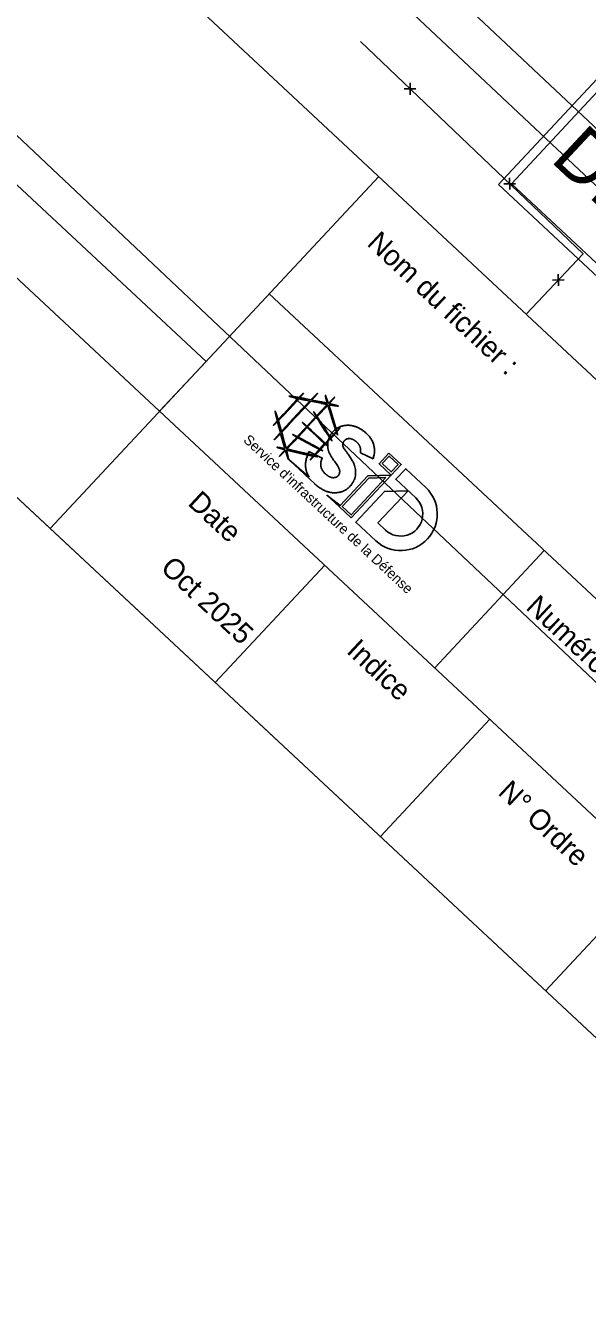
# Model space of a CAD drawing. Extents: x 343997 to 344255, y 298512 to 298767.
# Drawn here: x 344119.17 to 344139.61, y 298518.23 to 298564.4 of the extents above; entities that cross this region are included whole.
import ezdxf

# ---------------------------------------------------------------- set-up
doc = ezdxf.new("R2010")
doc.units = 0
for name, color, linetype in [('DH_CADRE -CARTOUCHE', 7, 'Continuous'), ('GO_DALLE', 7, 'Continuous'), ('PS_PLATE', 7, 'Continuous'), ('PS_WELD', 7, 'Continuous'), ('RES_TELEPHONE SOUTERRAIN', 7, 'Continuous')]:
    doc.layers.add(name, color=color, linetype=linetype)

msp = doc.modelspace()

# ---------------------------------------------------------------- linework, layer by layer
at = {"layer": 'DH_CADRE -CARTOUCHE'}
for p, q in [((344132.013, 298558.901), (344120.073, 298546.107)), ((344128.033, 298554.636), (344146.034, 298537.838)), ((344129.379, 298550.821), (344129.554, 298550.786)), ((344124.053, 298550.372), (344151.163, 298525.072)), ((344128.551, 298550.27), (344128.887, 298550.63)), ((344128.912, 298550.606), (344128.576, 298550.246)), ((344128.751, 298549.932), (344129.237, 298550.453)), ((344129.263, 298550.429), (344128.777, 298549.909)), ((344129.512, 298550.742), (344129.369, 298550.771)), ((344129.925, 298550.659), (344129.544, 298550.736)), ((344129.583, 298550.78), (344129.935, 298550.709)), ((344130.345, 298549.999), (344130.208, 298550.446)), ((344130.248, 298550.458), (344130.385, 298550.012)), ((344129.406, 298549.827), (344129.74, 298550.185)), ((344129.758, 298550.154), (344129.432, 298549.804)), ((344129.758, 298550.204), (344129.857, 298550.311)), ((344129.883, 298550.287), (344129.778, 298550.175)), ((344130.074, 298549.648), (344129.867, 298549.974)), ((344129.897, 298549.993), (344130.103, 298549.667)), ((344128.441, 298549.593), (344128.394, 298549.765)), ((344128.443, 298549.779), (344128.482, 298549.638)), ((344128.544, 298549.218), (344128.449, 298549.564)), ((344128.49, 298549.607), (344128.593, 298549.232)), ((344128.936, 298549.323), (344129.035, 298549.43)), ((344129.066, 298549.412), (344128.961, 298549.3)), ((344129.053, 298549.449), (344129.387, 298549.807)), ((344129.412, 298549.783), (344129.086, 298549.433)), ((344129.824, 298549.395), (344129.542, 298549.658)), ((344129.565, 298549.683), (344129.848, 298549.42)), ((344128.826, 298548.964), (344129.28, 298548.858)), ((344129.596, 298549.123), (344129.256, 298549.306)), ((344129.272, 298549.337), (344129.612, 298549.153)), ((344129.889, 298549.021), (344130.05, 298549.193)), ((344130.077, 298549.171), (344129.914, 298548.997)), ((344130.064, 298549.209), (344130.225, 298549.381)), ((344130.251, 298549.357), (344130.088, 298549.183)), ((344128.759, 298548.601), (344129.692, 298547.73)), ((344129.486, 298547.971), (344128.759, 298548.601)), ((344129.271, 298548.817), (344128.816, 298548.923)), ((344131.352, 298548.862), (344131.81, 298548.639)), ((344138.032, 298545.305), (344134.052, 298541.041)), ((344130.054, 298544.772), (344126.074, 298540.507)), ((344150.014, 298542.103), (344138.074, 298529.308)), ((344136.054, 298539.173), (344132.074, 298534.908))]:
    msp.add_line(p, q, dxfattribs=at)
for points in [[(343997.309, 298660.673), (344147.183, 298520.807), (344245.09, 298625.72), (344095.215, 298765.586)], [(344086.014, 298601.829), (344159.123, 298533.601), (344147.183, 298520.807), (344074.074, 298589.035)], [(344098.957, 298577.174), (344125.741, 298552.18), (344124.053, 298550.372), (344097.27, 298575.367)], [(344136.369, 298558.619), (344159.002, 298537.497), (344162.924, 298541.7), (344140.291, 298562.822)], [(344140.308, 298562.353), (344162.455, 298541.684), (344158.986, 298537.967), (344136.838, 298558.635)], [(344132.388, 298548.849), (344132.833, 298548.434), (344132.473, 298548.049), (344132.029, 298548.464)], [(344132.144, 298548.468), (344132.469, 298548.164), (344132.717, 298548.43), (344132.392, 298548.734)], [(344131.019, 298546.491), (344130.575, 298546.906), (344130.133, 298547.318), (344130.609, 298546.943), (344131.614, 298548.019), (344132.473, 298548.049)], [(344132.279, 298547.961), (344131.65, 298547.939), (344130.69, 298546.91), (344131.015, 298546.606)]]:
    msp.add_lwpolyline(points, close=True, dxfattribs=at)
for points in [[(344129.943, 298548.63), (344129.962, 298548.67), (344129.48, 298548.905)], [(344133.36, 298547.221), (344132.636, 298547.897), (344132.995, 298548.283), (344133.727, 298547.6)], [(344131.913, 298545.657), (344131.182, 298546.339), (344132.221, 298547.453), (344133.08, 298547.483), (344131.986, 298546.31), (344132.266, 298546.049)]]:
    msp.add_lwpolyline(points, dxfattribs=at)
for radius, start, end in [(1.329, 227.4033, 46.5536), (0.802, 226.9784, 46.9784)]:
    msp.add_arc((344132.813, 298546.635), radius, start, end, dxfattribs=at)
for points, degree in [([(344129.082, 298550.834), (344128.942, 298550.866), (344128.815, 298550.898), (344128.75, 298550.922)], 2), ([(344128.75, 298550.922), (344128.823, 298550.919), (344128.966, 298550.897), (344129.118, 298550.87)], 2), ([(344128.911, 298550.655), (344128.965, 298550.713), (344129.025, 298550.776), (344129.082, 298550.834)], 2), ([(344129.112, 298550.827), (344129.056, 298550.763), (344128.993, 298550.694), (344128.936, 298550.632)], 2), ([(344129.33, 298550.779), (344129.26, 298550.794), (344129.185, 298550.81), (344129.112, 298550.827)], 2), ([(344129.118, 298550.87), (344129.183, 298550.936), (344129.241, 298550.993), (344129.277, 298551.023)], 2), ([(344129.277, 298551.023), (344129.251, 298550.987), (344129.203, 298550.93), (344129.146, 298550.865)], 2), ([(344129.146, 298550.865), (344129.211, 298550.853), (344129.278, 298550.841), (344129.34, 298550.829)], 2), ([(344129.34, 298550.829), (344129.353, 298550.826), (344129.366, 298550.824), (344129.379, 298550.821)], 2), ([(344129.554, 298550.786), (344129.654, 298550.889), (344129.743, 298550.978), (344129.795, 298551.026)], 2), ([(344129.795, 298551.026), (344129.753, 298550.972), (344129.675, 298550.882), (344129.583, 298550.78)], 2), ([(344130.144, 298550.664), (344130.111, 298550.783), (344130.083, 298550.895), (344130.074, 298550.953)], 2), ([(344130.074, 298550.953), (344130.101, 298550.897), (344130.143, 298550.779), (344130.185, 298550.655)], 2), ([(344130.185, 298550.655), (344130.281, 298550.753), (344130.365, 298550.838), (344130.416, 298550.884)], 2), ([(344130.416, 298550.884), (344130.375, 298550.832), (344130.3, 298550.746), (344130.213, 298550.649)], 2), ([(344128.327, 298550.023), (344128.29, 298550.172), (344128.258, 298550.313), (344128.25, 298550.386)], 2), ([(344128.25, 298550.386), (344128.278, 298550.323), (344128.319, 298550.198), (344128.361, 298550.061)], 2), ([(344128.887, 298550.63), (344128.895, 298550.638), (344128.903, 298550.647), (344128.911, 298550.655)], 2), ([(344128.936, 298550.632), (344128.928, 298550.623), (344128.92, 298550.615), (344128.912, 298550.606)], 2), ([(344129.237, 298550.453), (344129.249, 298550.465), (344129.26, 298550.477), (344129.272, 298550.49)], 2), ([(344129.297, 298550.466), (344129.285, 298550.454), (344129.274, 298550.441), (344129.263, 298550.429)], 2), ([(344129.272, 298550.49), (344129.349, 298550.571), (344129.433, 298550.66), (344129.512, 298550.742)], 2), ([(344129.544, 298550.736), (344129.464, 298550.647), (344129.377, 298550.553), (344129.297, 298550.466)], 2), ([(344129.369, 298550.771), (344129.356, 298550.774), (344129.343, 298550.777), (344129.33, 298550.779)], 2), ([(344129.74, 298550.185), (344129.7, 298550.253), (344129.666, 298550.314), (344129.65, 298550.35)], 2), ([(344129.65, 298550.35), (344129.676, 298550.321), (344129.715, 298550.267), (344129.758, 298550.204)], 2), ([(344129.857, 298550.311), (344129.869, 298550.323), (344129.88, 298550.335), (344129.892, 298550.348)], 2), ([(344129.892, 298550.348), (344129.974, 298550.435), (344130.064, 298550.53), (344130.149, 298550.617)], 2), ([(344130.164, 298550.594), (344130.084, 298550.506), (344129.997, 298550.411), (344129.917, 298550.324)], 2), ([(344129.965, 298550.651), (344129.951, 298550.654), (344129.938, 298550.657), (344129.925, 298550.659)], 2), ([(344129.935, 298550.709), (344129.948, 298550.706), (344129.961, 298550.704), (344129.975, 298550.701)], 2), ([(344130.149, 298550.617), (344130.086, 298550.628), (344130.024, 298550.64), (344129.965, 298550.651)], 2), ([(344129.975, 298550.701), (344130.029, 298550.689), (344130.087, 298550.677), (344130.144, 298550.664)], 2), ([(344130.199, 298550.477), (344130.187, 298550.515), (344130.176, 298550.555), (344130.164, 298550.594)], 2), ([(344130.185, 298550.655), (344130.185, 298550.655), (344130.185, 298550.655), (344130.185, 298550.655)], 2), ([(344130.208, 298550.446), (344130.205, 298550.456), (344130.202, 298550.467), (344130.199, 298550.477)], 2), ([(344130.555, 298550.558), (344130.484, 298550.561), (344130.347, 298550.582), (344130.2, 298550.608)], 2), ([(344130.2, 298550.608), (344130.213, 298550.568), (344130.226, 298550.528), (344130.238, 298550.49)], 2), ([(344130.213, 298550.649), (344130.356, 298550.616), (344130.489, 298550.583), (344130.555, 298550.558)], 2), ([(344130.238, 298550.49), (344130.242, 298550.479), (344130.245, 298550.468), (344130.248, 298550.458)], 2), ([(344128.186, 298549.853), (344128.213, 298549.891), (344128.266, 298549.953), (344128.327, 298550.023)], 2), ([(344128.334, 298549.995), (344128.273, 298549.934), (344128.22, 298549.882), (344128.186, 298549.853)], 2), ([(344128.383, 298549.804), (344128.367, 298549.865), (344128.35, 298549.93), (344128.334, 298549.995)], 2), ([(344128.361, 298550.061), (344128.415, 298550.121), (344128.473, 298550.186), (344128.527, 298550.244)], 2), ([(344128.552, 298550.221), (344128.494, 298550.159), (344128.43, 298550.092), (344128.37, 298550.031)], 2), ([(344128.37, 298550.031), (344128.391, 298549.96), (344128.413, 298549.886), (344128.432, 298549.817)], 2), ([(344128.482, 298549.638), (344128.558, 298549.723), (344128.641, 298549.813), (344128.717, 298549.895)], 2), ([(344128.742, 298549.872), (344128.662, 298549.786), (344128.573, 298549.693), (344128.49, 298549.607)], 2), ([(344128.527, 298550.244), (344128.535, 298550.253), (344128.543, 298550.261), (344128.551, 298550.27)], 2), ([(344128.576, 298550.246), (344128.568, 298550.238), (344128.56, 298550.229), (344128.552, 298550.221)], 2), ([(344128.717, 298549.895), (344128.729, 298549.908), (344128.74, 298549.92), (344128.751, 298549.932)], 2), ([(344128.777, 298549.909), (344128.765, 298549.897), (344128.754, 298549.884), (344128.742, 298549.872)], 2), ([(344129.387, 298549.807), (344129.322, 298549.872), (344129.264, 298549.932), (344129.236, 298549.967)], 2), ([(344129.236, 298549.967), (344129.273, 298549.942), (344129.337, 298549.888), (344129.406, 298549.827)], 2), ([(344129.853, 298549.998), (344129.822, 298550.047), (344129.789, 298550.102), (344129.758, 298550.154)], 2), ([(344129.778, 298550.175), (344129.813, 298550.123), (344129.849, 298550.067), (344129.882, 298550.016)], 2), ([(344129.867, 298549.974), (344129.863, 298549.982), (344129.858, 298549.99), (344129.853, 298549.998)], 2), ([(344129.882, 298550.016), (344129.887, 298550.008), (344129.892, 298550), (344129.897, 298549.993)], 2), ([(344129.917, 298550.324), (344129.906, 298550.312), (344129.894, 298550.299), (344129.883, 298550.287)], 2), ([(344130.355, 298549.968), (344130.352, 298549.978), (344130.349, 298549.989), (344130.345, 298549.999)], 2), ([(344130.468, 298549.633), (344130.432, 298549.73), (344130.39, 298549.857), (344130.355, 298549.968)], 2), ([(344130.385, 298550.012), (344130.389, 298550.001), (344130.392, 298549.991), (344130.395, 298549.98)], 2), ([(344130.395, 298549.98), (344130.427, 298549.873), (344130.462, 298549.751), (344130.487, 298549.652)], 2), ([(344128.218, 298549.336), (344128.262, 298549.392), (344128.345, 298549.486), (344128.441, 298549.593)], 2), ([(344128.449, 298549.564), (344128.354, 298549.466), (344128.269, 298549.382), (344128.218, 298549.336)], 2), ([(344128.394, 298549.765), (344128.39, 298549.778), (344128.387, 298549.791), (344128.383, 298549.804)], 2), ([(344128.432, 298549.817), (344128.436, 298549.804), (344128.439, 298549.791), (344128.443, 298549.779)], 2), ([(344129.035, 298549.43), (344128.97, 298549.469), (344128.913, 298549.504), (344128.882, 298549.527)], 2), ([(344128.882, 298549.527), (344128.919, 298549.514), (344128.983, 298549.485), (344129.053, 298549.449)], 2), ([(344129.232, 298549.319), (344129.178, 298549.349), (344129.12, 298549.381), (344129.066, 298549.412)], 2), ([(344129.086, 298549.433), (344129.14, 298549.406), (344129.196, 298549.377), (344129.248, 298549.349)], 2), ([(344129.522, 298549.677), (344129.486, 298549.711), (344129.448, 298549.747), (344129.412, 298549.783)], 2), ([(344129.432, 298549.804), (344129.47, 298549.77), (344129.509, 298549.735), (344129.545, 298549.702)], 2), ([(344129.542, 298549.658), (344129.535, 298549.664), (344129.528, 298549.671), (344129.522, 298549.677)], 2), ([(344129.545, 298549.702), (344129.552, 298549.696), (344129.559, 298549.69), (344129.565, 298549.683)], 2), ([(344129.848, 298549.42), (344129.854, 298549.414), (344129.861, 298549.408), (344129.868, 298549.401)], 2), ([(344130.088, 298549.625), (344130.083, 298549.633), (344130.079, 298549.64), (344130.074, 298549.648)], 2), ([(344130.24, 298549.397), (344130.193, 298549.465), (344130.137, 298549.55), (344130.088, 298549.625)], 2), ([(344130.103, 298549.667), (344130.108, 298549.659), (344130.113, 298549.651), (344130.118, 298549.643)], 2), ([(344130.118, 298549.643), (344130.164, 298549.569), (344130.215, 298549.484), (344130.256, 298549.413)], 2), ([(344130.307, 298549.577), (344130.178, 298549.408), (344130.163, 298549.211)], 2), ([(344130.256, 298549.413), (344130.324, 298549.485), (344130.4, 298549.565), (344130.468, 298549.633)], 2), ([(344130.477, 298549.607), (344130.414, 298549.535), (344130.341, 298549.455), (344130.274, 298549.383)], 2), ([(344130.83, 298549.858), (344130.503, 298549.831), (344130.307, 298549.577)], 2), ([(344130.519, 298549.504), (344130.508, 298549.529), (344130.493, 298549.564), (344130.477, 298549.607)], 2), ([(344130.487, 298549.652), (344130.54, 298549.705), (344130.585, 298549.748), (344130.615, 298549.774)], 2), ([(344130.615, 298549.774), (344130.591, 298549.74), (344130.546, 298549.687), (344130.493, 298549.626)], 2), ([(344130.493, 298549.626), (344130.506, 298549.576), (344130.515, 298549.533), (344130.519, 298549.504)], 2), ([(344131.474, 298549.644), (344131.157, 298549.885), (344130.83, 298549.858)], 2), ([(344131.81, 298548.639), (344132.002, 298549.242), (344131.474, 298549.644)], 2), ([(344128.615, 298548.973), (344128.488, 298549.006), (344128.368, 298549.04), (344128.31, 298549.063)], 2), ([(344128.31, 298549.063), (344128.369, 298549.058), (344128.482, 298549.038), (344128.603, 298549.013)], 2), ([(344128.403, 298548.727), (344128.445, 298548.781), (344128.524, 298548.871), (344128.615, 298548.973)], 2), ([(344128.623, 298548.945), (344128.532, 298548.851), (344128.452, 298548.771), (344128.403, 298548.727)], 2), ([(344128.555, 298549.179), (344128.551, 298549.193), (344128.548, 298549.205), (344128.544, 298549.218)], 2), ([(344128.603, 298549.013), (344128.586, 298549.069), (344128.57, 298549.126), (344128.555, 298549.179)], 2), ([(344128.593, 298549.232), (344128.597, 298549.219), (344128.6, 298549.206), (344128.604, 298549.193)], 2), ([(344128.604, 298549.193), (344128.619, 298549.135), (344128.635, 298549.073), (344128.65, 298549.012)], 2), ([(344128.615, 298548.973), (344128.615, 298548.973), (344128.615, 298548.973), (344128.615, 298548.973)], 2), ([(344128.737, 298548.611), (344128.708, 298548.675), (344128.666, 298548.805), (344128.623, 298548.945)], 2), ([(344128.65, 298549.012), (344128.732, 298549.102), (344128.82, 298549.198), (344128.901, 298549.286)], 2), ([(344128.784, 298548.931), (344128.745, 298548.941), (344128.704, 298548.951), (344128.663, 298548.961)], 2), ([(344128.663, 298548.961), (344128.699, 298548.817), (344128.729, 298548.681), (344128.737, 298548.611)], 2), ([(344128.926, 298549.263), (344128.846, 298549.177), (344128.757, 298549.084), (344128.674, 298548.998)], 2), ([(344128.674, 298548.998), (344128.715, 298548.989), (344128.755, 298548.98), (344128.793, 298548.972)], 2), ([(344128.793, 298548.972), (344128.804, 298548.969), (344128.815, 298548.967), (344128.826, 298548.964)], 2), ([(344128.901, 298549.286), (344128.913, 298549.299), (344128.924, 298549.311), (344128.936, 298549.323)], 2), ([(344128.961, 298549.3), (344128.95, 298549.287), (344128.938, 298549.275), (344128.926, 298549.263)], 2), ([(344129.256, 298549.306), (344129.248, 298549.31), (344129.24, 298549.315), (344129.232, 298549.319)], 2), ([(344129.248, 298549.349), (344129.256, 298549.345), (344129.264, 298549.341), (344129.272, 298549.337)], 2), ([(344129.62, 298549.11), (344129.612, 298549.114), (344129.604, 298549.119), (344129.596, 298549.123)], 2), ([(344129.612, 298549.153), (344129.62, 298549.149), (344129.628, 298549.145), (344129.636, 298549.14)], 2), ([(344129.859, 298548.988), (344129.785, 298549.024), (344129.697, 298549.069), (344129.62, 298549.11)], 2), ([(344129.636, 298549.14), (344129.715, 298549.097), (344129.803, 298549.047), (344129.874, 298549.005)], 2), ([(344129.655, 298548.761), (344129.718, 298548.833), (344129.792, 298548.915), (344129.859, 298548.988)], 2), ([(344129.89, 298548.971), (344129.823, 298548.9), (344129.748, 298548.822), (344129.681, 298548.754)], 2), ([(344129.844, 298549.376), (344129.837, 298549.382), (344129.831, 298549.389), (344129.824, 298549.395)], 2), ([(344130.05, 298549.193), (344129.986, 298549.247), (344129.91, 298549.315), (344129.844, 298549.376)], 2), ([(344129.868, 298549.401), (344129.933, 298549.339), (344130.006, 298549.268), (344130.064, 298549.209)], 2), ([(344129.874, 298549.005), (344129.879, 298549.01), (344129.884, 298549.015), (344129.889, 298549.021)], 2), ([(344129.892, 298548.973), (344129.891, 298548.972), (344129.891, 298548.972), (344129.89, 298548.971)], 2), ([(344129.986, 298548.932), (344129.963, 298548.94), (344129.93, 298548.955), (344129.892, 298548.973)], 2), ([(344129.914, 298548.997), (344129.911, 298548.993), (344129.908, 298548.99), (344129.904, 298548.986)], 2), ([(344129.904, 298548.986), (344129.939, 298548.965), (344129.967, 298548.946), (344129.986, 298548.932)], 2), ([(344130.153, 298549.111), (344130.134, 298549.124), (344130.107, 298549.145), (344130.077, 298549.171)], 2), ([(344130.088, 298549.183), (344130.116, 298549.155), (344130.139, 298549.13), (344130.153, 298549.111)], 2), ([(344130.163, 298549.211), (344130.149, 298549.013), (344130.219, 298548.855)], 2), ([(344130.225, 298549.381), (344130.23, 298549.386), (344130.235, 298549.391), (344130.24, 298549.397)], 2), ([(344130.261, 298549.368), (344130.257, 298549.364), (344130.254, 298549.361), (344130.251, 298549.357)], 2), ([(344130.32, 298549.291), (344130.305, 298549.308), (344130.284, 298549.335), (344130.261, 298549.368)], 2), ([(344130.274, 298549.383), (344130.274, 298549.382), (344130.274, 298549.382), (344130.273, 298549.382)], 2), ([(344130.273, 298549.382), (344130.294, 298549.345), (344130.31, 298549.313), (344130.32, 298549.291)], 2), ([(344130.72, 298549.076), (344130.691, 298549.202), (344130.756, 298549.289)], 2), ([(344130.997, 298547.674), (344131.052, 298547.74), (344131.126, 298547.881), (344131.161, 298547.975), (344131.176, 298548.081), (344131.175, 298548.206), (344131.165, 298548.306), (344131.136, 298548.403), (344131.098, 298548.499), (344131.035, 298548.611), (344130.948, 298548.744), (344130.863, 298548.87), (344130.804, 298548.951), (344130.73, 298549.049), (344130.72, 298549.076)], 3), ([(344130.756, 298549.289), (344130.816, 298549.369), (344130.93, 298549.377)], 2), ([(344130.93, 298549.377), (344131.044, 298549.385), (344131.17, 298549.286)], 2), ([(344131.17, 298549.286), (344131.31, 298549.177), (344131.344, 298549.052)], 2), ([(344131.344, 298549.052), (344131.366, 298548.973), (344131.352, 298548.862)], 2), ([(344128.816, 298548.923), (344128.806, 298548.926), (344128.795, 298548.928), (344128.784, 298548.931)], 2), ([(344129.303, 298548.81), (344129.292, 298548.812), (344129.281, 298548.815), (344129.271, 298548.817)], 2), ([(344129.28, 298548.858), (344129.291, 298548.856), (344129.302, 298548.853), (344129.313, 298548.85)], 2), ([(344129.637, 298548.741), (344129.536, 298548.759), (344129.412, 298548.786), (344129.303, 298548.81)], 2), ([(344129.313, 298548.85), (344129.426, 298548.823), (344129.555, 298548.79), (344129.655, 298548.761)], 2), ([(344129.48, 298548.905), (344129.229, 298548.382), (344129.486, 298547.971)], 2), ([(344129.524, 298548.604), (344129.547, 298548.636), (344129.588, 298548.685), (344129.637, 298548.741)], 2), ([(344129.663, 298548.736), (344129.606, 298548.679), (344129.556, 298548.631), (344129.524, 298548.604)], 2), ([(344129.786, 298548.719), (344129.757, 298548.721), (344129.714, 298548.727), (344129.663, 298548.736)], 2), ([(344129.681, 298548.754), (344129.724, 298548.741), (344129.761, 298548.729), (344129.786, 298548.719)], 2), ([(344130.096, 298548.079), (344129.82, 298548.311), (344129.943, 298548.63)], 2), ([(344130.219, 298548.855), (344130.227, 298548.836), (344130.252, 298548.787), (344130.325, 298548.666), (344130.422, 298548.533), (344130.525, 298548.391), (344130.532, 298548.373)], 3), ([(344130.359, 298547.956), (344130.239, 298547.958), (344130.096, 298548.079)], 2), ([(344130.55, 298548.039), (344130.479, 298547.953), (344130.359, 298547.956)], 2), ([(344130.532, 298548.373), (344130.592, 298548.258), (344130.596, 298548.199)], 2), ([(344130.596, 298548.199), (344130.601, 298548.102), (344130.55, 298548.039)], 2), ([(344129.692, 298547.73), (344129.717, 298547.707), (344129.743, 298547.685)], 2), ([(344129.743, 298547.685), (344130.095, 298547.392), (344130.441, 298547.407)], 2), ([(344130.441, 298547.407), (344130.786, 298547.421), (344130.997, 298547.674)], 2)]:
    msp.add_open_spline(points, degree=degree, dxfattribs=at)
at = {"layer": 'GO_DALLE'}
msp.add_lwpolyline([(344145.36, 298571.324), (344150.236, 298566.706), (344141.289, 298557.281), (344123.303, 298574.184), (344132.335, 298583.661), (344140.996, 298575.54), (344140.93, 298575.464), (344141.582, 298574.891), (344141.725, 298575.026), (344141.55, 298575.188), (344141.782, 298575.465), (344142.714, 298574.538)], dxfattribs=at)
at = {"layer": 'PS_PLATE'}
msp.add_lwpolyline([(344125.459, 298574.243), (344141.227, 298559.424), (344148.086, 298566.649), (344132.39, 298581.516)], close=True, dxfattribs=at)
at = {"layer": 'PS_WELD'}
for p, q in [((344132.945, 298562.086), (344133.369, 298562.095)), ((344133.152, 298562.303), (344133.162, 298561.878)), ((344136.561, 298558.633), (344136.985, 298558.643)), ((344136.768, 298558.85), (344136.778, 298558.426)), ((344138.754, 298555.144), (344138.33, 298555.132)), ((344138.536, 298555.35), (344138.548, 298554.926))]:
    msp.add_line(p, q, dxfattribs=at)
msp.add_lwpolyline([(344131.348, 298563.817), (344139.442, 298556.09), (344137.371, 298553.901)], dxfattribs=at)
at = {"layer": 'RES_TELEPHONE SOUTERRAIN'}
msp.add_lwpolyline([(344006.37, 298666.609), (344159.504, 298522.019), (344160.824, 298520.82), (344163.6, 298518.226)], dxfattribs=at)

# ---------------------------------------------------------------- texts
at = {"layer": 'DH_CADRE -CARTOUCHE'}
for s, height, p in [('DIFFUSION RESTREINTE', 1.92832, (344138.214, 298559.485)), ('Nom du fichier :', 0.75, (344131.551, 298556.428)), ('DUBOIS SANDRINE', 0.0005, (344124.049, 298550.376)), ('DUBOIS SANDRINE', 0.0005, (344124.049, 298550.376)), ("Service d'infrastructure de la Défense", 0.36773, (344127.068, 298549.29)), ('Date', 0.75, (344125.042, 298546.992)), ('Oct 2025', 0.75, (344124.047, 298544.619)), ("Numéro d'opération :", 0.75, (344137.325, 298543.204)), ('Indice', 0.75, (344130.806, 298541.613)), ('N° Ordre', 0.75, (344136.313, 298536.473))]:
    msp.add_text(s, height=height, rotation=316.9784, dxfattribs=at).set_placement(p)

doc.saveas('drawing.dxf')
